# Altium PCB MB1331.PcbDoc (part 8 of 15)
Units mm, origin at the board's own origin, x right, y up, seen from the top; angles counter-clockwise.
Board outline 169.25 x 173.25 mm, 6 copper layers (Top Layer, Signal Layer 1, Signal Layer 2, Signal Layer 3, Signal Layer 4, Bottom Layer), stack 1.556 mm thick; 871 components, 699 nets, 3244 pads, 2370 vias.
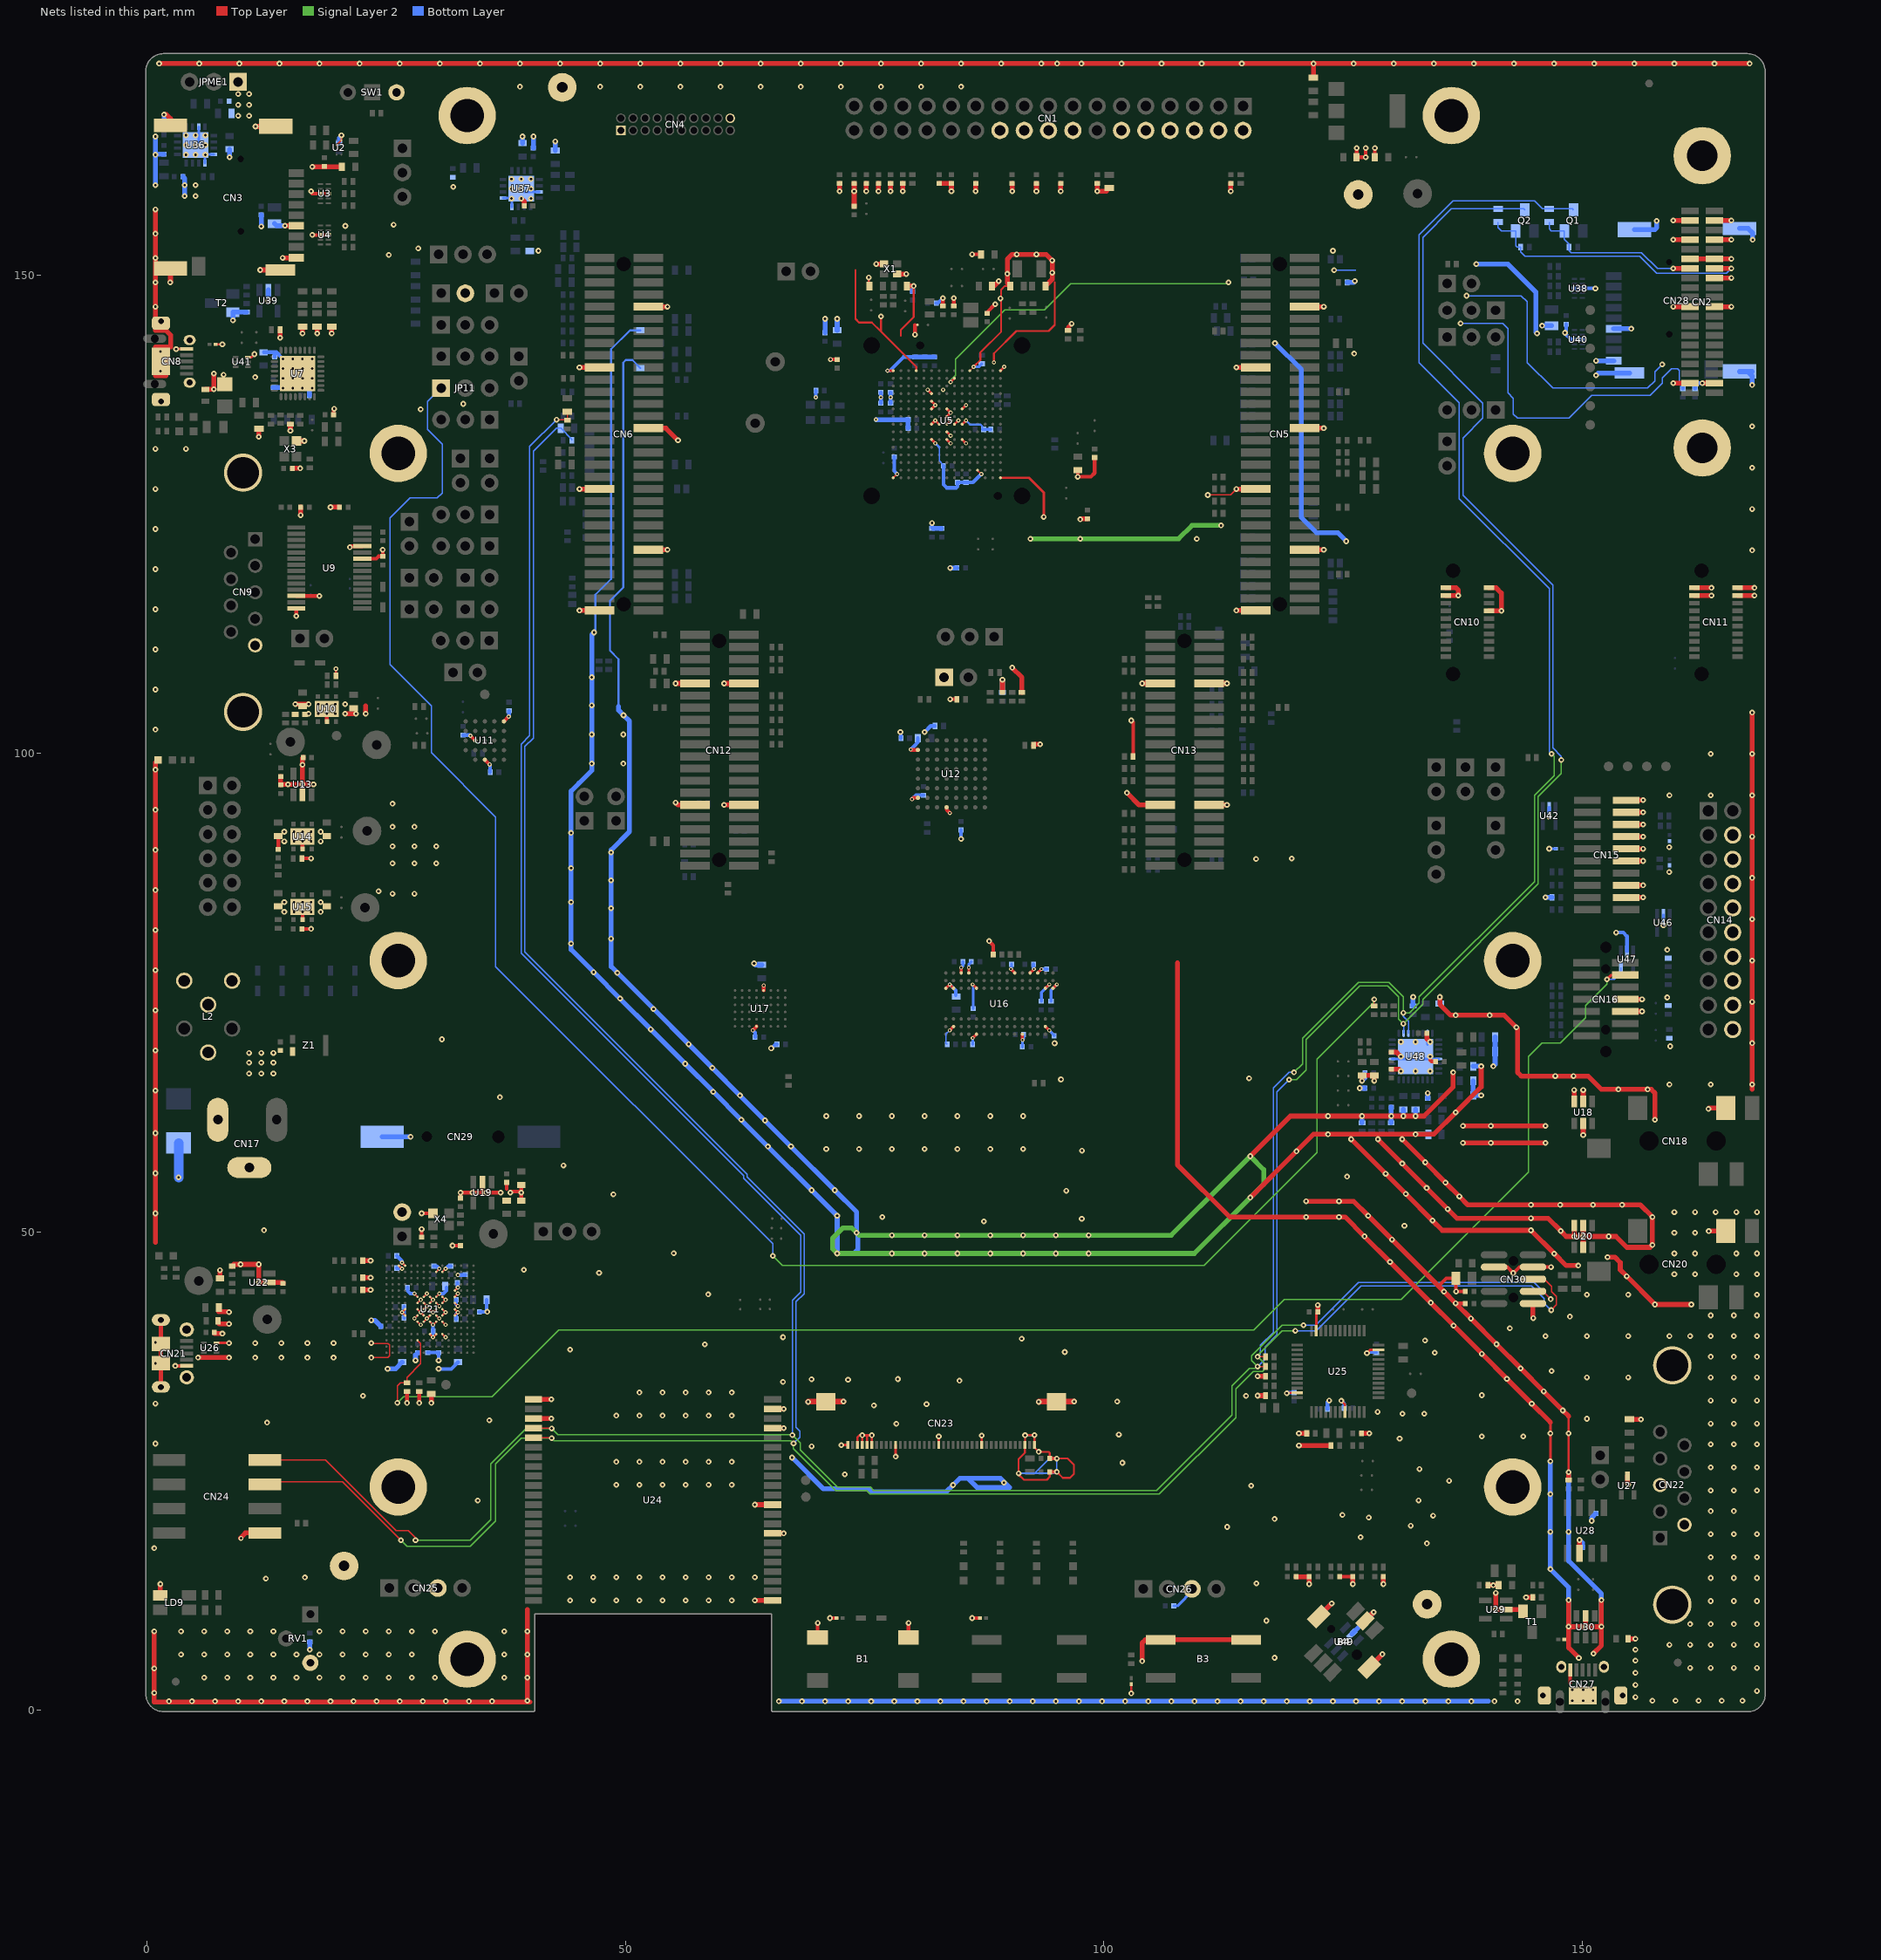
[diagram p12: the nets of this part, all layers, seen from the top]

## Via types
v1: diameter 0.6, hole 0.254, Top Layer to Bottom Layer, tented both sides, 1747 vias
v2: diameter 0.45, hole 0.2, Top Layer to Bottom Layer, tented both sides, 272 vias
v3: diameter 0.406, hole 0.203, Top Layer to Bottom Layer, tented both sides, 160 vias
v4: diameter 0.6, hole 0.25, Top Layer to Bottom Layer, tented both sides, 82 vias
v5: diameter 0.45, hole 0.25, Top Layer to Bottom Layer, tented both sides, 45 vias
v6: diameter 0.5, hole 0.25, Top Layer to Bottom Layer, tented both sides, 23 vias
v7: diameter 1.016, hole 0.508, Top Layer to Bottom Layer, tented both sides, 17 vias
v8: diameter 0.508, hole 0.254, Top Layer to Bottom Layer, tented both sides, 9 vias
v9: diameter 0.61, hole 0.305, Top Layer to Bottom Layer, tented both sides, 7 vias
v10: diameter 0.5, hole 0.254, Top Layer to Bottom Layer, tented both sides, 6 vias
v11: diameter 0.4, hole 0.2, Top Layer to Bottom Layer, tented both sides, 1 vias
v12: diameter 0.483, hole 0.254, Top Layer to Bottom Layer, tented both sides, 1 vias

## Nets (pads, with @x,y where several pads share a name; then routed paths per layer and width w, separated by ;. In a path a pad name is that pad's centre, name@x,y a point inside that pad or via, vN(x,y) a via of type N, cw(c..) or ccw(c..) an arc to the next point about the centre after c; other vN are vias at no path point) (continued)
GND: B1.1 B1.2 B3.3 B3.4 B4.5 B4.7 B4.8 C1.1 C2.1 C3.2 C4.1 C5.1 C6.1 C7.1 C8.1 C9.1 C10.1 C11.1 C12.1 C13.1 C14.1 C15.1 C16.1 C17.1 C18.1 C19.1 C20.1 C21.1 C22.1 C23.1 C24.1 C25.1 C26.1 C27.1 C28.1 C29.1 C30.2 C31.2 C32.1 C33.2 C34.1 C35.2 C37.1 C38.1 C39.2 C41.2 C42.2 C43.2 C44.1 C45.2 C46.1 C47.1 C48.1 C49.2 C50.1 C51.2 C52.1 C53.1 C54.2 C55.2 C56.1 C58.1 C59.1 C60.2 C61.2 C62.2 C63.2 C64.1 C65.1 C66.1 C67.1 C68.1 C69.1 C70.1 C71.1 C72.2 C73.2 C74.2 C75.1 C76.2 C77.1 C78.1 C79.1 C80.1 C81.1 C82.1 C83.1 C84.1 C85.1 C86.1 C87.1 C88.1 C89.1 C90.1 C91.1 C92.2 C93.2 C94.1 C95.1 C96.2 C97.2 C98.2 C99.2 C100.2 C101.2 C102.1 C103.2 C104.2 C105.1 C106.1 C107.1 C108.1 C109.1 C110.2 C111.2 C112.2 C113.2 C114.1 C115.1 C116.2 C117.2 C118.1 C119.2 C120.2 C121.2 C122.2 C123.2 C124.2 C125.2 C126.2 C127.2 C128.2 C129.2 C130.2 C131.1 C132.1 C133.1 C134.2 C135.1 C136.2 C137.2 C138.2 C139.2 C140.2 C141.2 C142.1 C143.2 C144.1 C145.2 C146.2 C147.1 C149.2 C150.2 C152.2 C153.2 C154.2 C155.2 C156.2 C157.2 C158.2 C160.1 C161.1 C162.2 C163.1 C165.2 C166.2 C167.2 C168.1 C171.1 C172.1 C173.1 C174.1 C175.1 C176.1 C177.1 C178.1 C179.1 C180.1 C181.1 C182.1 C183.1 C184.1 C185.1 C186.1 C187.1 C188.1 C189.1 C190.1 C191.1 C192.1 C193.1 C194.1 C195.1 C196.2 C197.2 C198.1 C199.2 C200.1 C201.1 CN1.2 CN1.4 CN1.6 CN1.8 CN1.10 CN1.12 CN1.16 CN1.18 CN1.20 CN1.22 CN2.3 CN2.4 CN2.7 CN2.8 CN2.11 CN2.12 CN2.16 CN2.21 CN2.22 CN2.37 CN2.38 CN2.41 CN2.42 CN3.6 CN3.9 CN3.11 CN3.12 CN3.13 CN3.14 CN4.1 CN4.20 CN5.10 CN5.19 CN5.30 CN5.39 CN5.50 CN5.59 CN6.10 CN6.19 CN6.30 CN6.39 CN6.50 CN6.59 CN7.2 CN8.5 CN8.6 CN8.7 CN8.8 CN8.9 CN8.10 CN9.5 CN9.MT1 CN9.MT2 CN10.13 CN10.18 CN10.19 CN10.20 CN11.17 CN11.18 CN11.19 CN11.20 CN12.9 CN12.10 CN12.29 CN12.30 CN13.9 CN13.10 CN13.29 CN13.30 CN14.4 CN14.6 CN14.8 CN14.10 CN14.12 CN14.14 CN14.16 CN14.18 CN14.20 CN15.3 CN15.5 CN15.9 CN15.11 CN15.13 CN15.15 CN15.17 CN15.19 CN16.5 CN16.7 CN18.3 CN19.2 CN20.3 CN21.5 CN21.6 CN21.7 CN21.8 CN21.9 CN21.10 CN21.11 CN22.3 CN22.6 CN22.MT1 CN22.MT2 CN23.1 CN23.3 CN23.12 CN23.21 CN23.30 CN23.35 CN23.36 CN23.37 CN23.38 CN23.40 CN23.MT1 CN23.MT2 CN24.2 CN25.3 CN26.3 CN27.5 CN27.6 CN27.7 CN27.8 CN27.9 CN27.10 CN28.6 CN28.9 CN28.11 CN28.12 CN28.13 CN28.14 CN29.2 CN30.1 CN30.7 CN30.8 H1.1 H2.1 H3.1 H4.1 H5.1 H6.1 H7.1 H8.1 H9.1 H10.1 JP25.1 JPME1.1 L2.4 L2.5 L2.6 LD7.2 LD9.1 R1.1 R7.1 R25.1 R26.1 R27.1 R28.2 R30.2 R37.2 R40.1 R86.1 R90.1 R92.1 R100.2 R107.1 R109.1 R129.2 R147.2 R148.2 R151.1 R154.1 R163.2 R164.1 R165.1 R167.2 R169.1 R171.1 R172.1 R175.2 R188.2 R191.1 R198.1 R199.1 R200.1 R232.1 R251.2 R336.1 R346.1 R393.1 R395.1 R400.1 R402.2 R408.1 R410.1 R412.1 R414.1 R416.1 R419.2 R420.1 RV1.3 SB10.1 SW1.3 T1.2 T2.2 TPG1.1 TPG2.1 TPG3.1 TPG4.1 U2.2 U2.8 U3.3 U3.8 U4.3 U4.8 U5.A1 U5.A15 U5.D14 U5.E1 U5.F6 U5.F8 U5.F10 U5.G2 U5.G8 U5.H6 U5.H7 U5.H8 U5.H9 U5.H10 U5.J8 U5.K4 U5.K5 U5.K6 U5.K8 U5.K10 U5.M1 U5.R1 U5.R15 U6.2 U7.33 U8.2 U9.12 U9.14 U9.23 U9.25 U10.2 U10.EP U11.B3 U11.C1 U11.E5 U12.E8 U12.H2 U12.H7 U13.2 U14.2 U14.EP U15.2 U15.EP U16.A3 U16.B3 U16.B8 U16.C1 U16.D1 U16.E9 U16.F1 U16.L3 U16.L9 U16.M1 U16.N1 U16.P3 U16.P8 U16.R3 U17.D1 U17.E6 U18.2 U18.5 U18.6 U19.2 U20.2 U20.5 U20.6 U21.D5 U21.D6 U21.D7 U21.D8 U21.D9 U21.F2 U21.F6 U21.F7 U21.F8 U21.F9 U21.F10 U21.F12 U21.G2 U21.G6 U21.G7 U21.G8 U21.G9 U21.G10 U21.G12 U21.H6 U21.H7 U21.H8 U21.H9 U21.H10 U21.H12 U21.J6 U21.J7 U21.J8 U21.J9 U21.J10 U21.K6 U21.K7 U21.K8 U21.K9 U21.K10 U21.M1 U21.M8 U21.M9 U21.N1 U22.2 U23.2 U24.1 U24.3 U24.23 U24.30 U24.33 U24.41 U24.43 U25.8 U25.23 U25.35 U25.47 U26.3 U27.3 U28.2 U29.2 U30.2 U31.2 U32.2 U33.2 U34.2 U35.2 U36.7 U36.12 U36.13 U36.17 U37.7 U37.12 U37.13 U37.17 U38.3 U38.8 U39.2 U40.3 U40.8 U41.3 U42.2 U43.2 U44.2 U45.2 U46.2 U47.2 U48.7 U48.13 U48.28 U48.33 U49.2 X1.2 X1.4 X3.2 X4.2 | length 1998.9
  Top Layer w0.1: U5.E1@86,140 v2(86.4,140.4)
  Top Layer w0.127: v1(23.431,36.862) 25.158,36.862 25.35,37.054 25.35,38.191 25.191,38.35 23.467,38.35 v1(23.431,38.386) ; U5.D14@86.8,129.6 v2(87.2,129.2) ; v1(110.871,127) 110.905,127.034 113.25,127.034 v1(113.85,127.635) ; CN16.5@154.492,73.048 CN16.5@154.5,73.04 ; CN16.7@154.492,74.318 CN16.7@154.5,74.31
  Top Layer w0.2: U21.N1@26.325,46.475 v2(26.65,46.15) ; v2(26.65,46.8) U21.M1@26.975,46.475 ; U21.M9@26.975,41.275 v2(26.65,41.6) U21.M8@26.975,41.925 ; v2(27.95,40.95) U21.K9@28.275,41.275 ; v2(27.95,43.55) U21.K6@28.275,43.225 ; U21.K10@28.275,40.625 v2(28.6,40.3) ; U21.K8@28.275,41.925 v2(28.6,41.6) U21.J9@28.925,41.275 ; U21.K7@28.275,42.575 v2(28.6,42.9) ; U21.J10@28.925,40.625 v2(29.25,40.95) U21.H9@29.575,41.275 ; U21.J8@28.925,41.925 v2(29.25,42.25) U21.J7@28.925,42.575 ; U21.J6@28.925,43.225 v2(29.25,43.55) ; U21.H12@29.575,39.325 v2(29.9,39) U21.G12@30.225,39.325 ; U21.H10@29.575,40.625 v2(29.9,40.3) U21.G10@30.225,40.625 ; U21.H8@29.575,41.925 v2(29.9,41.6) U21.G8@30.225,41.925 ; U21.H7@29.575,42.575 v2(29.9,42.9) U21.H6@29.575,43.225 ; U21.G9@30.225,41.275 v2(30.55,40.95) ; U21.G7@30.225,42.575 v2(30.55,42.25) ; U21.G6@30.225,43.225 v2(30.55,43.55) ; U21.G2@30.225,45.825 v2(30.55,46.15) ; U21.F12@30.875,39.325 v2(31.2,39) ; U21.F10@30.875,40.625 v2(31.2,40.3) ; U21.F9@30.875,41.275 v2(31.2,41.6) U21.F8@30.875,41.925 ; U21.F7@30.875,42.575 v2(31.2,42.9) U21.F6@30.875,43.225 ; U21.F2@30.875,45.825 v2(31.2,46.15) ; U21.D9@32.175,41.275 v2(32.5,41.6) U21.D8@32.175,41.925 ; U21.D7@32.175,42.575 v2(32.5,42.25) ; U21.D6@32.175,43.225 v2(32.5,43.55) ; U21.D5@32.175,43.875 v2(32.5,44.2) ; CN12.10@62.373,107.3 CN12.10@62.373,107.315 ; 74.041,150.495 74.041,145.415 74.422,145.034 75.766,145.034 76.708,144.092 ; v1(75.438,149.733) 75.438,148.906 C22.1@75.5,148.844 ; v1(76.708,145.669) 76.708,144.092 ; 78.796,143.647 78.796,144.25 80.137,145.591 v1(80.137,148.844) ; U5.M1@80.4,140 80.4,140.4 76.708,144.092 ; v2(86.4,140.4) 87.1,141.1 87.1,141.9 89.281,144.081 89.281,148.463 89.662,148.844 C25.1@90.232,148.844 ; CN23.12@87.25,27.738 v1(87.25,28.725) ; C29.1@87.8,146 C29.1@87.8,146.093 ; v2(88.519,140.843) 88.519,141.8 90.864,144.145 94.234,144.145 94.869,144.78 94.869,149.225 ; C200.1@94.358,24.927 94.358,24.408 94.05,24.1 91.65,24.1 91.1,24.65 v1(91.1,24.775) 91.1,26.272 91.75,26.922 CN23.3@91.75,27.738 91.775,27.763 v1(91.775,28.75) 91.8,28.775 v1(92.75,28.775) CN23.1@92.75,27.738 92.75,27.475 v1(93.2,27.025) 94.25,27.025 94.358,26.917 C201.1@94.358,26.327 ; v1(95.1,24.925) 95.725,24.3 96.475,24.3 96.875,24.7 96.875,25.675 96.225,26.325 v1(95.1,26.325) ; CN16.5@154.5,73.04 CN16.5@154.532,73.085 ; CN16.7@154.5,74.31 CN16.7@154.532,74.355
  Top Layer w0.203: U2.2@19.816,163.572 U2.8@20.316,164.072 20.316,164.588 v1(20.32,164.592) ; U5.R15@78,128.8 v2(78.4,129.2) ; R30.2@96.266,144.214 96.266,144.526
  Top Layer w0.25: U41.3@10.556,141.412 10.912,141.412 v1(11.225,141.725) ; v1(72.575,27.725) 72.588,27.738 CN23.40@73.25,27.738 ; CN23.38@74.25,27.738 74.25,28.525 74.475,28.75 v1(74.75,28.75) ; CN23.37@74.75,27.738 v1(74.75,28.75) ; CN23.36@75.25,27.738 75.25,28.725 75.225,28.75 ; CN23.35@75.75,27.738 v1(75.75,28.75) 75.225,28.75 ; v1(78.25,26.525) CN23.30@78.25,27.738 ; CN23.21@82.75,27.738 v1(82.75,28.625) ; v1(74.75,28.75) 75.225,28.75
  Top Layer w0.254: v1(3.048,142.24) 3.078,142.27 CN8.5@4.13,142.27 ; U6.2@7.17,142.748 v1(7.874,142.748) ; U26.3@7.25,38.4 8.558,38.4 v1(8.572,38.386) ; R90.1@19.75,108.1 v6(19.75,108.85) ; v2(77.4,140) U5.R1@78,140 ; v2(81.6,138) U5.K4@82,137.6 ; v2(82.4,134.8) U5.J8@82.8,134.4 ; U5.H10@83.6,132.8 v2(84,132.4) ; U5.H9@83.6,133.6 v2(84,133.2) ; U5.H8@83.6,134.4 v2(84,134.8) ; U5.H7@83.6,135.2 v2(84,135.6) U5.H6@83.6,136 ; v2(84,138.8) U5.G2@84.4,139.2 ; U5.G8@84.4,134.4 v2(84.8,134.8) ; U5.F10@85.2,132.8 v2(85.6,132.4) ; U5.F8@85.2,134.4 v2(85.6,134.8) ; U5.F6@85.2,136 v2(85.6,136.4) ; U5.A15@89.2,128.8 92.18,128.8 93.726,127.254 v1(93.726,124.714) ; U5.A1@89.2,140 v2(89.6,140.4) ; v1(102.87,1.778) U35.2@102.87,2.736 ; v1(119.126,33.147) 119.162,33.183 U25.47@120.21,33.183 ; U25.35@122.21,39.683 122.21,41.496 C73.2@122.37,41.656 ; v1(124.829,32.357) 125.21,31.976 U25.8@125.21,31.183 ; v1(127.508,37.338) 127.853,37.683 U25.23@128.71,37.683 ; v1(146.685,26.035) v1(146.685,28.956) 146.685,30.099 ; v1(148.59,24.892) v1(148.59,28.956) 148.59,30.734 ; v1(163.195,62.865) v1@163.275,62.945
  Top Layer w0.3: U5.K10@82,132.8 v2(82.4,132.4) ; U5.K8@82,134.4 v2(82.4,134.8) ; U5.K6@82,136 v2(82.4,136.4) U5.K5@82,136.8
  Top Layer w0.305: U16.R3@83.497,75.463 v3(83.897,75.863) U16.P3@84.297,75.463 ; v3(83.896,71.063) U16.P8@84.297,71.463 ; U16.N1@85.097,77.063 v3(85.097,77.622) ; U16.M1@85.897,77.063 v3(85.897,77.622) ; v3(86.296,70.263) U16.L9@86.697,70.663 ; v3(86.296,75.863) U16.L3@86.696,75.463 ; v3(90.297,77.463) U16.F1@90.697,77.063 ; v3@91.497,70.066 U16.E9@91.497,70.663 ; U16.D1@92.297,77.063 v3(92.696,77.463) ; U16.C1@93.097,77.063 v3(93.496,77.463) ; U16.B8@93.897,71.463 v3(94.297,71.063) ; U16.B3@93.897,75.463 v3(94.296,75.863) ; U16.A3@94.697,75.463 v3(95.097,75.863)
  Top Layer w0.381: v1(2.953,36.005) 2.957,36 CN21.5@4.15,36 ; v1(15.6,114.35) U9.14@15.6,115.155 ; U9.12@15.6,116.455 v1@18.02,116.455 ; C54.2@16.198,81.661 v1(17.145,81.661) ; R129.2@16.198,89.027 v1(17.145,89.027) ; U15.2@16.256,82.647 v1(16.256,83.439) U15.EP@16.256,83.947 ; v1(17.145,158.75) 17.399,158.496 ; v1(17.272,154.178) U4.8@18.132,154.178 U4.3@18.952,154.178 ; v1@17.272,158.496 17.399,158.496 ; U10.2@18.796,103.348 v1(18.796,104.14) ; U3.3@18.952,158.496 U3.8@18.132,158.496 17.399,158.496 ; C32.1@19.5,135.382 19.5,135.959 v1(19.558,136.017) ; v1(21.209,121.539) 21.325,121.655 U9.25@22.5,121.655 ; U9.23@22.5,120.355 23.962,120.355 24.199,120.592 C41.2@24.638,120.592 v1(24.638,121.285) ; v1(27.178,32.131) R164.1@27.178,33.332 ; v1(28.448,32.131) R165.1@28.448,33.332 ; C68.1@28.702,49.472 v1(28.702,50.292) ; v1(28.702,51.943) 28.712,51.933 X4.2@29.909,51.933 ; v1(31.935,48.572) C69.1@32.766,48.572 ; C65.1@32.766,53.536 v1(32.766,54.102) v1(34.036,54.102) 35.052,54.102 ; v2(33.812,101.84) U11.B3@34.306,101.346 ; U19.2@35.052,55.202 35.052,54.102 ; U11.C1@35.306,99.346 v2(35.8,98.852) ; v1(36.957,54.102) v1(35.433,54.102) 35.052,54.102 ; U11.E5@37.306,103.346 v2(37.8,103.84) ; 37.592,54.483 C64.1@37.592,55.176 ; v1@37.973,54.229 v1@39.116,54.229 ; C67.1@39.116,53.532 v1(39.116,54.102) v1@39.116,54.229 ; C63.2@39.116,54.926 v1@39.116,54.229 ; v3(63.316,71.069) 63.703,71.456 U17.E6@63.703,71.48 ; U17.D1@64.453,75.23 v3(64.452,75.762) ; B1.1@70.093,7.637 70.093,9.133 v1(70.104,9.144) ; v1(71.374,9.652) U31.2@72.078,9.652 ; v6(71.443,141.166) C30.2@72.136,141.166 ; B1.2@79.593,7.637 79.593,9.133 v1(79.604,9.144) ; v3(79.827,100.419) 79.88,100.366 U12.H2@80.567,100.366 ; v3(79.953,95.212) 80.107,95.366 U12.H7@80.567,95.366 ; v1(80.264,143.764) 80.264,144.78 ; C27.1@83.185,147.004 v1(83.185,147.574) ; U12.E8@83.567,94.366 83.567,94.125 v3(83.915,93.777) ; v1(83.947,105.664) R92.1@84.64,105.664 ; C28.1@84.328,146.754 v1(84.328,147.574) ; v1(86.233,9.652) U32.2@87.064,9.652 ; v1(86.233,152.146) C21.1@87.184,152.146 ; C29.1@87.8,146.093 v1(88.646,146.939) ; v1(88.011,80.391) 88.45,79.952 C55.2@88.45,78.994 ; C200.1@94.358,24.927 95.098,24.927 v1(95.1,24.925) ; C201.1@94.358,26.327 95.098,26.327 v1(95.1,26.325) ; 96.266,144.526 v1(96.647,144.907) ; C33.2@97.282,129.602 v1(97.282,128.905) 98.655,128.905 99.05,129.3 C35.2@99.05,130.925 ; v1(102.87,103.441) 103.066,103.246 R109.1@103.066,99.695 ; C82.1@124.656,13.97 C83.1@126.042,13.97 ; v4(126.43,163.257) C1.1@126.43,162.306 v4(127.381,162.306) v4(127.381,163.257) ; C2.1@128.332,162.306 v4(128.332,163.257) ; v4(134.112,68.326) 134.112,67.945 134.239,67.818 C59.1@134.678,67.818 ; 134.962,44.362 135.012,44.362 135.8,45.15 C75.1@136.8,45.15 136.8,43.8 v1(136.825,43.775) C76.2@137.8,43.775 ; v1(136.775,42.549) 136.799,42.525 C79.1@137.8,42.525 ; CN30.8@140.795,46.33 142.17,46.33 v1(142.8,45.7) 142.835,45.7 143.465,46.33 CN30.7@144.865,46.33 146.745,46.33 v1(146.75,46.325) ; 148.755,2.855 CN27.5@148.755,4.23
  Top Layer w0.4: C51.2@13.716,89.985 C49.2@13.716,91.375 ; U14.2@16.256,90.013 v1(16.256,90.805) U14.EP@16.256,91.313 ; v1(18.796,104.14) U10.EP@18.796,104.648
  Top Layer w0.5: CN21.8@1.45,33.8 CN21.9@1.45,40.8 ; v6@9.779,18.034 10.29,18.545 CN24.2@12.308,18.545 ; v1(113.85,114.935) CN5.59@115.872,114.935 ; v1(113.85,140.335) CN5.19@115.872,140.335 ; CN5.50@120.972,121.285 v1(122.994,121.285) ; CN5.30@120.972,133.985 v1(122.994,133.985) ; CN30.1@144.865,42.52 144.865,41.035 v1(144.9,41)
  Top Layer w0.508: v1(0.762,8.255) v1(0.762,4.381) v1(0.762,1.841) 0.762,0.889 v1@40.005,0.889 ; 0.889,48.895 v1(0.889,51.943) v1(0.889,56.134) v1(0.889,60.325) v1(0.889,64.77) v1(0.889,68.961) v1(0.889,73.152) v1(0.889,77.343) v1(0.889,81.534) v1(0.889,85.725) v1(0.889,89.916) v1(0.889,94.107) v1(0.889,98.298) 0.889,99.048 LD7.2@1.155,99.314 ; v1(0.889,156.845) v1(0.889,154.305) v1(0.889,151.765) v1(0.889,149.225) v1(0.889,146.685) 0.889,144.224 1.957,144.224 2.471,143.709 2.471,142.466 0.889,142.466 0.889,139.474 1.957,139.474 ; v1(1.27,172.085) v1(5.461,172.085) v1(9.652,172.085) v1(13.843,172.085) v1(18.034,172.085) v1(22.225,172.085) v1(26.416,172.085) v1(30.607,172.085) v1(34.798,172.085) v1(38.989,172.085) v1(43.18,172.085) v1(47.371,172.085) v1(51.562,172.085) v1(55.753,172.085) v1(59.944,172.085) v1(64.135,172.085) v1(68.326,172.085) v1(72.517,172.085) v1(76.708,172.085) v1(80.899,172.085) v1(85.09,172.085) v1(89.281,172.085) v1(93.472,172.085) v1(95.123,172.085) v1(97.663,172.085) v1(101.854,172.085) v1(106.045,172.085) v1(110.236,172.085) v1(114.427,172.085) v1(121.92,172.085) ; LD9.1@1.377,12.028 1.397,12.048 v1(1.397,13.208) ; v1(1.397,139.954) 1.455,140.012 CN8.10@1.455,140.97 1.397,141.028 v1(1.397,141.986) ; v1(1.778,166.751) 2.032,166.751 2.45,166.333 CN3.12@2.45,165.615 ; v1(2.413,149.225) 2.45,149.262 CN3.11@2.45,150.665 ; v1(5.334,36.862) v1(8.572,36.862) ; U8.2@6.096,138.039 6.975,138.039 v1(6.985,138.049) v1(6.985,139.7) ; C74.2@7.054,39.37 v1(7.874,39.37) ; C72.2@7.483,41.656 8.541,41.656 v1(8.572,41.624) ; U23.2@7.558,40.386 v1(8.572,40.386) ; C70.1@7.62,45.15 v1(7.62,46.006) ; R148.2@8.89,46.424 9.075,46.609 v1(9.779,46.609) v1(11.684,46.609) v1(11.684,44.704) U22.2@12.784,44.704 14.166,44.704 C71.1@14.224,44.646 ; v1(11.337,165.515) CN3.13@13.45,165.515 ; v1(11.684,133.096) R37.2@11.684,133.92 ; v1(11.831,150.515) CN3.14@13.95,150.515 ; v1(13.912,143.441) R28.2@13.912,144.272 ; C48.1@13.97,96.716 C47.1@13.97,97.594 ; C48.1@14.028,96.774 v1(14.732,96.774) v1(16.256,96.774) ; v1(14.17,151.79) CN3.9@15.6,151.79 ; v1(14.424,155.14) CN3.6@15.6,155.14 ; v1(14.986,133.731) R40.1@14.986,134.424 ; C34.1@15.182,129.794 v1(16.002,129.794) ; v1(15.494,105.156) v1(16.891,105.156) ; X3.2@15.611,132.651 v1(16.446,132.651) ; v1(16.06,124.899) C37.1@16.06,125.73 ; U13.2@16.256,95.674 v1(16.256,96.774) ; v1(16.256,143.891) R25.1@16.256,144.588 ; C46.1@16.314,99.568 16.256,99.51 v1(16.256,98.806) v1(16.256,96.774) ; v1(17.272,161.29) C3.2@18.542,161.29 ; v1(17.399,96.774) v1(16.256,96.774) ; v1(17.78,143.891) R26.1@17.78,144.588 ; C3.2@18.542,161.348 C3.2@18.542,161.29 ; v1(19.177,125.73) C38.1@20.124,125.73 ; v1(19.304,143.891) R27.1@19.304,144.588 ; C4.1@20.382,161.29 C3.2@18.542,161.29 ; v1(20.701,104.14) v1(21.844,104.14) ; R154.1@22.548,43.942 v1(23.368,43.942) ; R151.1@22.548,45.212 v1(23.368,45.212) ; R147.2@22.548,46.99 v1(23.368,46.99) ; v1(22.86,104.14) 22.86,104.96 ; v1(29.718,32.131) C77.1@29.718,33.082 ; v1(39.116,157.988) 39.428,157.676 C19.1@39.428,157.226 ; v1(39.751,1.016) v1(39.751,3.429) v1(39.751,5.842) v1(39.751,8.255) 39.751,10.541 ; U24.3@40.4,30.5 v1(42.271,30.5) ; U24.1@40.4,32.5 v1(42.271,32.5) ; v1(45.2,114.935) CN6.59@47.293,114.935 ; v1(45.2,127.635) CN6.39@47.293,127.635 ; v1(45.2,140.335) CN6.19@47.293,140.335 ; CN6.50@52.393,121.285 v1(54.4,121.285) ; CN6.30@52.393,133.985 54.229,133.985 v1(55.499,132.715) ; CN6.10@52.393,146.685 v1(54.4,146.685) ; v1(55.245,94.869) 55.499,94.615 CN12.29@57.273,94.615 ; v1(55.251,107.315) CN12.9@57.273,107.315 ; v1(60.325,94.615) CN12.30@62.373,94.615 ; v1(60.325,107.315) CN12.10@62.373,107.315 ; v1(63.529,11.5) U24.23@65.4,11.5 ; v1(63.529,21.5) U24.33@65.4,21.5 ; U24.41@65.396,29.504 U24.41@65.4,29.5 v1(66.544,29.5) ; U24.30@65.4,18.5 65.404,18.496 v1(66.548,18.496) ; U24.43@65.4,31.5 65.404,31.496 v1(66.548,31.496) ; v1(72.39,158.75) C5.1@72.39,159.57 ; C20.1@73.914,157.168 v1(73.914,158.75) C6.1@73.914,159.57 ; v1(75.184,158.75) C7.1@75.184,159.57 ; v1(76.217,151.147) X1.2@77.049,151.147 ; v1(76.454,158.75) C8.1@76.454,159.57 ; v1(77.724,158.75) C9.1@77.724,159.57 ; X1.4@78.399,150.097 v1(79.358,150.097) ; v1(78.994,158.75) C10.1@78.994,159.57 ; C23.1@79.44,148.844 v1(80.137,148.844) ; C11.1@82.804,159.57 C12.1@84.074,159.57 v1(84.074,158.75) ; v1(86.614,158.75) C13.1@86.614,159.57 ; C24.1@88.33,148.844 88.519,148.844 v1(89.027,149.352) ; C43.2@89.408,106.368 v1(89.408,107.696) ; C25.1@90.232,148.844 89.916,149.16 v1(89.916,150.114) 89.916,151.638 90.424,152.146 v1(92.964,152.146) 93.98,152.146 v1(94.615,151.511) v1(94.615,150.241) 94.615,149.541 C26.1@93.918,148.844 ; v1(90.424,108.966) 91.44,107.95 R86.1@91.44,106.368 ; v1(90.424,158.75) C14.1@90.424,159.57 ; R107.1@92.652,100.838 92.779,100.965 v1(93.345,100.965) ; v1(92.964,158.75) C15.1@92.964,159.57 ; v1(95.504,158.75) C16.1@95.504,159.57 ; v1(97.536,124.46) 97.594,124.518 C39.2@98.298,124.518 ; C17.1@99.314,159.57 v1(99.314,158.75) 100.268,158.75 R7.1@100.584,159.066 ; v1(102.425,95.885) 103.696,94.615 CN13.29@105.892,94.615 ; v1(104.013,5.143) 104.013,7.048 104.355,7.39 B3.4@105.968,7.39 B3.3@114.868,7.39 ; v1(104.013,107.315) CN13.9@105.892,107.315 ; 107.696,78.105 107.696,57.023 113.157,51.562 v1(121.158,51.562) v1(124.587,51.562) 125.222,51.562 v1(127.249,49.535) v1(129.923,46.861) v1(134.18,42.604) v1(136.57,40.214) v1(139.525,37.259) v1(142.133,34.651) v1(144.736,32.048) 146.685,30.099 ; CN13.30@110.992,94.615 v1(112.881,94.615) ; CN13.10@110.992,107.315 v1(112.881,107.315) ; v1(113.284,158.75) C18.1@113.284,159.57 ; v1(113.85,127.635) CN5.39@115.872,127.635 ; v1(115.316,53.594) v1(120.142,58.42) 121.92,60.198 v1(123.444,60.198) v1(132.588,60.198) 134.493,60.198 v1(136.779,62.484) 139.446,65.151 v1(139.446,67.31) ; v1(115.316,57.912) 119.507,62.103 v1(123.444,62.103) v1(127,62.103) v1(130.048,62.103) v1(131.318,62.103) v1(132.588,62.103) 133.477,62.103 136.525,65.151 v1(136.525,66.675) ; v1(116.078,32.893) R167.2@116.898,32.893 ; v1(116.078,34.925) R163.2@116.898,34.925 ; C80.1@120.084,13.97 C81.1@121.47,13.97 v1(121.47,13.208) ; v1(120.396,27.686) R172.1@123.756,27.686 ; v1(120.396,28.956) R171.1@121.216,28.956 ; CN5.10@120.972,146.685 v1(122.994,146.685) ; v1(121.158,53.213) v1(124.587,53.213) 126.111,53.213 v1(127.635,51.689) v1(130.125,49.199) 134.962,44.362 v1(135.564,43.76) v1(136.775,42.549) ; R1.1@121.92,170.626 v1(121.92,172.085) ; C73.2@122.37,41.656 v1(122.37,42.36) ; B4.7@122.459,9.818 123.818,11.176 v1(123.825,11.176) ; v1(125.857,59.69) v1(129.464,56.083) v1(131.572,53.975) v1(134.357,51.19) 135.382,50.165 v1(144.653,50.165) v1(147.088,47.73) 148.336,46.482 v1(149.606,46.482) ; v1(126.042,13.208) C83.1@126.042,13.97 ; C78.1@126.942,28.956 v1(127.762,28.956) ; v1(127,65.786) C60.2@127,66.356 C61.2@128.27,66.356 v1(128.27,65.786) ; B4.5@127.303,9.358 v1(128.213,10.268) ; B4.8@127.763,4.514 129.121,5.873 v1(129.128,5.873) ; v1(128.651,59.69) v1(131.198,57.143) v1(133.749,54.592) v1(135.949,52.392) 136.906,51.435 v1(144.653,51.435) 146.431,51.435 v1(147.762,50.104) 148.336,49.53 v1(149.164,49.53) ; v1(129.228,13.208) C84.1@129.228,13.97 ; C62.2@130.048,66.998 130.868,66.998 v4(131.064,66.802) ; C58.1@130.048,68.776 130.614,68.776 v4(131.064,68.326) ; v1(131.191,59.69) v1(133.604,57.277) v1(135.723,55.158) v1(137.172,53.709) 138.049,52.832 v1(144.653,52.832) v1(147.701,52.832) v1(151.13,52.832) v1(154.178,52.832) 156.083,52.832 v1(157.353,51.562) v1(157.353,48.641) 157.099,48.387 154.686,48.387 153.543,49.53 v1(152.781,49.53) v1(150.114,49.53) ; C56.1@133.788,70.751 133.788,70.174 v4(134.112,69.85) ; v1(135.128,74.549) 135.128,73.787 136.271,72.644 v1(136.779,72.644) v1(140.335,72.644) 141.859,72.644 v1(143.129,71.374) 143.256,71.247 143.256,66.675 143.637,66.294 v1(147.193,66.294) v1(149.098,66.294) 150.622,66.294 152.019,64.897 v1(153.797,64.897) v1(156.845,64.897) 157.226,64.897 157.607,64.516 v1(157.607,61.722) ; CN10.18@135.75,116.5 v1(137.062,116.5) 137.062,117.065 136.827,117.3 CN10.20@135.75,117.3 ; v1@136.799,42.525 v1(138.376,40.948) v1(141.051,38.273) v1(143.574,35.75) v1(145.982,33.342) v1(147.978,31.346) 148.59,30.734 ; v1(137.541,59.309) v1(140.462,59.309) v1(146.177,59.309) ; v1(137.541,61.087) v1(140.462,61.087) v1(146.177,61.087) ; R188.2@140.15,13.081 v1(140.716,13.081) C85.1@141.286,13.081 ; CN10.13@140.25,114.9 v1(141.562,114.9) 141.562,116.756 141.018,117.3 CN10.19@140.25,117.3 ; v1(140.97,12.287) v1@140.97,10.668 ; T1.2@143.83,10.371 143.66,10.541 U29.2@142.07,10.541 v1@141.097,10.541 ; v1(144.145,11.811) R191.1@144.838,11.811 ; v1(148.59,11.525) v1(148.59,8.763) v1@148.59,8.534 ; R175.2@148.59,24.072 v1(148.59,24.892) ; U20.6@149.164,50.68 v1(149.164,49.53) ; U18.6@149.164,63.634 v1(149.164,64.836) ; v1(149.657,5.486) 148.59,6.553 v1@148.59,8.534 ; U28.2@149.733,16.421 v1(149.733,17.812) ; U20.2@150.114,48.38 v1(150.114,49.53) ; U20.5@150.114,50.68 v1(150.114,49.53) ; v1(150.114,60.132) U18.2@150.114,61.334 ; U18.5@150.114,63.634 v1(150.114,64.836) ; U30.2@150.368,9.837 v1(150.368,8.738) ; v1(151.181,5.944) 152.019,6.782 v1(152.019,8.763) v1(152.019,11.525) ; v1@151.892,8.738 v1(150.368,8.738) ; v1(152.654,47.371) 153.416,47.371 153.987,46.799 153.987,46.038 v1(154.656,45.369) v1(157.607,42.418) v1(161.417,42.418) ; CN16.5@154.5,73.04 v1(156.267,73.04) ; CN16.7@154.5,74.31 v1(156.267,74.31) ; CN15.3@154.608,84.955 v1(156.375,84.955) ; CN15.5@154.608,86.225 v1(156.375,86.225) ; CN15.9@154.608,88.765 v1(156.375,88.765) ; CN15.11@154.608,90.035 v1(156.375,90.035) ; CN15.13@154.608,91.305 v1(156.375,91.305) ; CN15.15@154.608,92.575 v1(156.375,92.575) ; CN15.17@154.608,93.845 v1(156.375,93.845) ; CN15.19@154.608,95.115 v1(156.375,95.115) ; v1@154.727,23.708 U27.3@154.727,24.47 ; U33.2@154.803,7.493 v1(155.575,7.493) ; R169.1@154.94,30.418 v1(156.148,30.418) ; v1(159.513,138.685) CN2.37@161.28,138.685 ; v1(159.513,146.685) CN2.21@161.28,146.685 ; v1(159.513,153.685) CN2.7@161.28,153.685 ; v1(159.513,155.685) CN2.3@161.28,155.685 ; CN2.11@161.28,151.685 CN2.12@163.83,151.685 v1(165.597,151.685) ; CN11.18@161.75,116.5 v1(163.517,116.5) ; CN11.20@161.75,117.3 v1(163.517,117.3) ; v1(162.56,138.684) 162.561,138.685 CN2.38@163.83,138.685 ; v1(163.237,50.08) CN20.3@165,50.08 ; v1@163.275,62.945 CN18.3@165.005,62.945 ; CN2.22@163.83,146.685 v1(165.597,146.685) ; CN2.16@163.83,149.685 v1(165.597,149.685) ; CN2.8@163.83,153.685 v1(165.597,153.685) ; CN2.4@163.83,155.685 v1(165.597,155.685) ; CN11.17@166.25,116.5 v1(168.017,116.5) ; CN11.19@166.25,117.3 v1(168.017,117.3) ; v1(167.513,172.085) v1(163.83,172.085) v1(159.639,172.085) v1(155.448,172.085) v1(151.257,172.085) v1(147.066,172.085) v1(142.875,172.085) v1(138.684,172.085) v1(134.493,172.085) v1(130.302,172.085) v1(126.111,172.085) v1(121.92,172.085) ; 167.767,64.897 v1(167.767,65.405) v1(167.767,69.723) v1(167.767,74.041) v1(167.767,78.359) v1(167.767,82.677) v1(167.767,86.995) v1(167.767,91.313) v1(167.767,95.631) v1(167.767,99.949) v1(167.767,104.267) ; v1@140.97,10.668 v1@141.097,10.541 ; v1@140.97,10.668 v1(140.97,10.541) v1@141.097,10.541 ; v1@148.59,8.534 148.793,8.738 v1(150.368,8.738) ; v1(149.164,49.53) v1(150.114,49.53)
  Top Layer w0.6: v1(69.1,32.25) 69.112,32.263 CN23.MT2@70.95,32.263 72.788,32.263 v1(72.8,32.275) ; v1(93.2,32.25) 93.212,32.263 CN23.MT1@95.05,32.263 96.888,32.263 v1(96.9,32.275)
  Signal Layer 2 w0.127: v2(84,138.8) 84,139 84.5,139.5 84.5,141.2 89.668,146.368 93.789,146.368 96.52,149.098 112.903,149.098 v1(113.03,149.225)
  Signal Layer 2 w0.508: v1(92.329,122.428) v1(97.536,122.428) 107.823,122.428 109.22,123.825 v1(112.268,123.825) ; 71.65,48.238 v1(72.136,47.752) v1(77.851,47.752) v1(81.28,47.752) v1(84.709,47.752) v1(88.138,47.752) v1(91.567,47.752) v1(94.996,47.752) v1(98.425,47.752) 109.474,47.752 v1(115.316,53.594) 116.713,54.991 116.713,56.515 v1(115.316,57.912) 112.903,55.499 107.061,49.657 v1(98.425,49.657) v1(94.996,49.657) v1(91.567,49.657) v1(88.138,49.657) v1(84.709,49.657) v1(81.28,49.657) v1(77.851,49.657) 74.422,49.657 v1(74.168,49.911) 73.654,50.425 72.75,50.425 71.65,49.325 71.65,48.238
  Bottom Layer w0.127: 82.8,132 82.8,130.56 83.243,130.117 C125.2@83.243,130.048 ; C155.2@83.439,69.781 C155.2@83.509,69.711 ; C155.2@83.624,69.596 C155.2@83.509,69.711 ; v3(83.896,71.063) 83.509,70.675 C155.2@83.509,69.711 ; 92.748,24.775 94.298,26.325 v1(95.1,26.325) v1(95.1,24.925) ; v1(124.079,150.495) 126.365,150.495 ; v1(137.3,144.934) 141.705,144.934 142.24,144.399 142.24,137.668 142.8,137.108 142.8,135.475 143.25,135.025 148.614,135.025 151.003,137.414 157.099,137.414 158.37,138.685 158.37,139.257 159.321,140.208 159.957,140.208 160.147,140.017 160.147,138.812 ; v1(137.922,147.828) 143.637,147.828 144.272,147.193 144.272,140.843 146.939,138.176 156.845,138.176 157.607,138.938 157.607,139.891 v1(158.369,140.653)
  Bottom Layer w0.2: v2(26.65,41.6) 26.795,41.6 26.866,41.529 ; v2(29.9,39) C186.1@29.9,39.65 v2(29.9,40.3) ; v2(30.55,43.55) v2@30.65,43.55 ; v2@32.5,41.586 v2(32.5,41.6) ; v1(91.1,24.775) 92.748,24.775 94.95,24.775 v1(95.1,24.925) ; v1(91.775,28.75) 91.8,28.775 v1(92.75,28.775)
  Bottom Layer w0.203: v1(46.736,112.649) 46.863,112.776 46.863,116.586 48.514,118.237 48.514,142.24 50.484,144.21 C103.2@51.562,144.21 ; 49.276,104.902 49.276,109.855 48.387,110.744 48.387,115.951 49.784,117.348 49.784,140.843 50.038,141.097 50.735,141.097 C106.1@51.562,140.27 ; v2(85.6,134.8) 86.034,134.366 87.122,134.366 87.318,134.17 C123.2@87.318,133.858
  Bottom Layer w0.254: U36.17@5.405,163.901 U36.7@5.405,165.476 ; U36.13@6.055,161.676 6.055,162.601 U36.12@6.98,162.601 ; U37.13@37.216,158.029 38.141,158.029 U37.12@38.141,157.104 ; U37.17@39.441,158.679 U37.7@41.016,158.679 ; v2(82.4,132.4) 82.8,132 ; v1(127.508,37.338) 127.566,37.396 C189.1@128.524,37.396 ; U48.28@130.163,68.076 U48.33@132.338,68.076 ; U48.33@132.838,68.076 U48.13@135.013,68.076 ; U48.33@133.838,69.576 U48.7@133.838,70.751 ; v1(146.558,90.043) U44.2@147.262,90.043 ; v1(158.496,82.042) U46.2@158.496,83.146
  Bottom Layer w0.3: C123.2@87.318,133.858 C123.2@87.445,133.858 C122.2@88.196,133.858 ; C198.1@107.315,10.923 107.69,10.923 109.34,12.573 CN26.3@109.22,12.7
  Bottom Layer w0.305: v3(85.097,77.622) 85.286,77.812 C139.2@85.286,78.232 ; v3(85.897,77.622) 85.897,77.965 C138.2@86.164,78.232 ; v3(86.296,70.263) 86.302,70.258 C154.2@86.302,69.596 ; C149.2@86.36,73.348 v3@86.36,75.8 ; v2(86.4,140.4) 86.933,140.4 R251.2@87.249,140.716 ; v3(90.297,77.463) 90.366,77.533 C141.2@90.366,77.978 ; C158.2@91.498,69.342 91.498,70.042 v3(91.51,70.053) 91.636,70.18 C150.2@91.636,70.612 ; C146.2@93.472,74.11 93.472,75.039 v3(94.296,75.863) ; v3(94.297,71.063) 94.811,70.549 C152.2@94.811,70.485 ; C145.2@94.488,74.11 94.488,75.255 v3(95.097,75.863)
  Bottom Layer w0.381: C105.1@12.192,141.924 13.516,141.924 v1(14.22,141.22) ; C110.2@13.335,141.42 13.335,141.743 ; R199.1@20.066,163.772 20.066,164.338 v1(20.32,164.592) ; C175.1@26.104,46.228 26.572,46.228 v2(26.65,46.15) ; C171.1@26.104,47.498 26.65,46.952 v2(26.65,46.8) ; C183.1@26.866,41.021 26.866,41.529 C181.1@26.866,42.164 ; C178.1@27.236,44.196 27.236,43.82 27.506,43.55 v2(27.95,43.55) ; C191.1@29.337,37.396 C190.1@30.48,37.396 v1(30.48,36.576) ; v2(29.9,39) v2(29.9,40.3) ; C174.1@29.972,46.424 30.276,46.424 v2(30.55,46.15) ; v1(30.48,35.687) 30.483,35.684 31.812,35.684 C187.1@32.512,36.384 ; v2@30.65,43.55 30.977,43.55 31.307,43.88 C177.1@31.307,44.196 ; v2(31.2,46.15) 31.474,46.424 C173.1@31.75,46.424 ; C184.1@32.316,40.894 32.316,41.402 v2@32.5,41.586 ; C180.1@32.316,42.926 32.316,42.434 v2(32.5,42.25) ; C176.1@32.443,44.704 32.443,44.257 v2(32.5,44.2) ; C132.1@33.02,101.912 33.74,101.912 v2(33.812,101.84) ; C172.1@33.25,45.5 C172.1@33.274,45.524 ; C182.1@34.74,41.656 v1(35.56,41.656) 35.498,41.718 C179.1@35.498,42.926 ; v2(35.8,98.852) 35.872,98.78 C135.1@35.872,98.044 ; v2(37.8,103.84) 37.846,103.886 C131.1@37.846,104.452 ; v3(63.316,71.069) 63.558,70.827 C153.2@63.558,70.358 ; v9@65.202,69.146 v9(65.246,69.19) 65.652,69.596 C156.2@65.844,69.596 ; v2(69.908,137.2) C116.2@69.908,137.922 ; C119.2@76.708,136.594 v2(76.708,137.2) C113.2@76.708,137.726 ; v2(77.4,140) 77.643,140 79.063,141.42 C109.1@80.264,141.42 ; C118.1@77.724,136.594 v2(77.724,137.2) C112.2@77.724,137.726 ; C124.2@78.105,130.995 78.105,129.495 v2(78.4,129.2) ; v1(78.74,102.235) 78.798,102.177 C134.2@78.798,101.6 ; v3(79.953,95.212) 80.374,95.633 C136.2@81.167,95.633 ; 80.334,100.876 79.876,100.419 v3(79.827,100.419) 80.58,101.172 C133.1@80.58,101.6 ; v1(81.28,102.235) 81.915,102.87 R346.1@82.354,102.87 ; C129.2@82.042,123.64 v1(82.042,124.079) ; C99.2@82.492,147.066 82.677,147.066 v1(83.185,147.574) ; C125.2@83.243,130.048 83.243,128.085 83.566,127.762 84.582,127.762 84.709,127.889 C127.2@84.709,128.328 C126.2@85.598,128.328 86.328,128.328 v2(87.2,129.2) ; v3(83.897,75.863) 84.525,75.235 C144.1@84.525,74.752 ; v1(85.09,91.059) C137.2@85.09,92.006 ; C140.2@92.652,77.978 92.652,77.508 v3(92.696,77.463) ; v3(93.496,77.463) 93.503,77.47 C143.2@94.038,77.47 ; v1(119.126,33.147) 119.195,33.216 C193.1@119.888,33.216 ; C195.1@123.386,31.496 123.386,32.2 v1(123.571,32.385) ; v1(124.829,32.357) 125.141,32.045 C194.1@125.141,31.595 ; v1(146.558,93.409) U42.2@146.558,94.322 ; v1(148.209,143.954) v1@148.209,143.891 ; C101.2@148.336,144.838 148.336,144.018 v1@148.209,143.891 ; U38.3@149.196,148.59 U38.8@150.016,148.59 v1(151.384,148.59) ; U40.8@150.016,143.256 U40.3@149.196,143.256 148.844,143.256 v1@148.209,143.891 ; v1(153.543,81.28) 154.305,81.28 154.686,80.899 U47.2@154.686,79.336 ; v1(159.513,138.685) 160.273,138.685 160.528,138.43 C115.1@160.528,138.118 ; C114.1@161.798,138.118 161.798,138.43 162.052,138.684 v1(162.56,138.684)
  Bottom Layer w0.4: v2(32.5,45.5) C172.1@33.25,45.5
  Bottom Layer w0.5: v1(117.894,142.875) 120.65,140.119 120.65,124.65 122.237,123.063 124.46,123.063 v1(125.349,122.174)
  Bottom Layer w0.508: v1(0.889,159.385) v1(0.889,162.56) ; v1(0.889,164.465) v1(0.889,162.56) ; C90.1@1.778,162.618 0.947,162.618 v1(0.889,162.56) ; C87.1@1.778,165.55 v1(1.778,166.751) ; C93.2@3.752,160.274 3.937,160.089 v1(3.937,159.385) v1(3.937,158.242) ; v1(8.636,162.306) C88.1@8.636,163.13 ; v1(8.974,145.245) T2.2@8.974,146.116 10.406,146.116 R232.1@10.414,146.108 ; v1(11.938,155.067) C95.1@11.938,156.268 ; v1(12.7,147.32) U39.2@12.7,148.42 ; C111.2@13.208,138.234 14.158,138.234 v1(14.22,138.172) ; C94.1@13.335,155.36 13.555,155.14 v1(14.424,155.14) ; C117.2@16.96,137.414 16.96,137.864 v1(17.268,138.172) ; v1(17.018,6.35) C199.2@17.018,7.17 ; v1(23.431,40.767) 23.807,40.767 C185.1@24.442,40.132 ; CN29.2@24.566,59.944 v1(27.559,59.944) ; v1(25.146,35.687) 25.149,35.684 26,35.684 26,35.714 C188.1@26.67,36.384 ; v1(28.067,36.576) 28.067,37.142 C192.1@28.321,37.396 ; C89.1@39.243,163.768 v1(39.243,164.465) ; C91.1@40.386,163.264 v1(40.386,164.465) ; R200.1@42.672,163.006 v1(42.672,163.957) ; 45.149,96.883 44.323,96.057 v1(44.323,91.694) v1(44.323,88.011) v1(44.323,84.455) v1(44.323,80.137) 44.323,79.502 v1(46.688,77.137) v1(49.443,74.382) v1(52.655,71.17) v1(56.251,67.574) v1(59.182,64.643) v1(62.113,61.712) v1(64.897,58.928) v1(69.469,54.356) v1(72.136,51.689) v1(72.136,47.752) 73.877,47.752 74.3,48.175 74.3,49.779 v1(74.168,49.911) 74.168,52.07 v1(71.882,54.356) v1(67.306,58.932) v1(64.588,61.65) v1(61.985,64.253) v1(59.096,67.142) v1(56.617,69.621) v1(52.94,73.298) v1(49.153,77.085) 48.514,77.724 v1(48.514,80.645) v1(48.514,83.82) v1(48.514,86.741) v1(48.514,89.662) 48.514,89.916 50.419,91.821 50.419,103.378 v1(49.807,103.99) 49.276,104.521 49.276,104.902 ; 45.149,96.883 46.482,98.216 v1(46.482,98.933) v1(46.482,101.981) v1(46.482,105.029) v1(46.482,107.95) 46.482,112.395 v1(46.736,112.649) ; v9(63.443,78.054) 63.581,77.916 C142.1@64.262,77.916 ; v1(66.04,0.953) v1(68.453,0.953) v1(70.866,0.953) v1(73.279,0.953) v1(75.692,0.953) v1(78.105,0.953) v1(80.518,0.953) v1(82.931,0.953) v1(85.344,0.953) v1(87.757,0.953) v1(90.17,0.953) v1(92.583,0.953) v1(94.996,0.953) v1(97.409,0.953) v1(99.822,0.953) v1(102.235,0.953) v1(104.648,0.953) v1(107.061,0.953) v1(109.474,0.953) v1(111.887,0.953) v1(114.3,0.953) v1(116.713,0.953) v1(119.126,0.953) v1(121.539,0.953) v1(123.952,0.953) v1(126.365,0.953) v1(128.778,0.953) v1(131.191,0.953) v1(133.604,0.953) v1(136.017,0.953) v1(138.43,0.953) 140.208,0.953 ; v1(67.425,26.425) 70.7,23.15 75.425,23.15 75.725,22.85 83.55,22.85 v1(84.25,23.55) 84.95,24.25 85.8,24.25 ; C104.2@70.866,143.96 v1(70.866,145.415) ; C102.1@72.136,144.21 v1(72.136,145.415) ; v2(76.2,134.874) C120.2@79.56,134.874 C121.2@79.56,133.985 ; C98.2@80.01,148.278 80.01,148.717 v1(80.137,148.844) ; C109.1@80.264,141.42 C108.1@81.28,141.42 C107.1@82.296,141.42 ; C129.2@82.169,123.513 C128.2@83.058,123.513 ; v1(83.947,119.38) C130.2@84.64,119.38 ; R336.1@89.408,106.368 v1(89.408,107.696) ; C97.2@125.418,149.225 126.111,149.225 v1(126.238,149.352) ; U49.2@125.924,7.979 v1(128.213,10.268) ; v1(126.746,65.024) C162.2@127.312,65.024 ; R419.2@127,61.41 v1(127,62.103) ; v1(127,65.786) 127.312,66.098 R414.1@127.312,66.548 ; R416.1@130.048,61.41 v1(130.048,62.103) C168.1@130.048,63.05 ; v1(131.318,62.103) C166.2@131.318,62.8 ; R402.2@132.334,73.602 v1(132.334,74.549) ; v1(132.588,60.198) R420.1@133.92,60.198 ; v1(132.588,62.103) C165.2@132.588,62.8 ; C167.2@133.858,63.95 v1(133.858,64.516) ; C147.1@135.128,73.852 v1(135.128,74.549) ; C161.1@138.622,65.786 C163.1@138.622,64.262 v1(139.446,64.262) ; C160.1@138.622,67.31 v1(139.446,67.31) ; v1(138.938,151.13) 142.24,151.13 145.167,148.203 145.167,144.012 v1(145.288,143.891) ; v1(140.716,67.31) 140.908,67.502 R412.1@140.908,68.834 R410.1@140.908,70.358 ; v1(145.821,144.692) C100.2@146.812,144.692 ; v1(146.177,84.963) R393.1@146.87,84.963 ; v1(146.685,26.035) v1(146.685,22.606) v1(146.685,18.669) v1(146.685,14.764) 148.59,12.859 v1(148.59,11.525) v1(148.59,8.763) ; v1(148.59,24.892) v1(148.59,18.669) 148.59,15.621 152.019,12.192 v1(152.019,11.525) v1(152.019,8.763) ; v1(149.733,17.812) 150.045,17.5 C197.2@150.045,17.018 ; v1(151.003,19.812) 151.003,20.135 C196.2@151.442,20.574 ; v1(151.447,139.51) 151.69,139.752 CN28.14@154.951,139.752 ; v1(151.447,141.034) 151.454,141.027 CN28.9@153.301,141.027 ; CN28.6@153.301,144.377 v1(155.13,144.377) ; CN28.13@155.451,154.752 157.609,154.752 157.797,154.94 v1(157.797,155.638) ; CN28.11@166.451,139.902 CN28.11@167.311,139.902 ; CN28.12@166.451,154.852 167.347,154.852 167.831,154.368 v1(167.831,153.67) ; CN28.11@167.756,139.902 CN28.11@167.311,139.902 ; v1(167.767,138.493) 167.767,139.446 CN28.11@167.311,139.902 ; 85.8,24.25 89.2,24.25 90.15,23.3 86.75,23.3 85.8,24.25
  Bottom Layer w1: v1(3.3,55.7) C157.2@3.3,59.3
  other v1: 2.286,0.953 4.699,0.953 7.112,0.953 9.525,0.953 11.938,0.953 14.351,0.953 16.764,0.953 19.177,0.953 21.59,0.953 24.003,0.953 26.416,0.953 28.829,0.953 31.242,0.953 33.655,0.953 36.068,0.953 140.843,0.953 143.256,0.953 148.971,1.016 150.114,1.016 151.13,1.016 157.353,1.016 159.766,1.016 162.179,1.016 164.592,1.016 166.751,1.016 155.575,1.397 168.275,2.032 148.971,2.159 150.114,2.159 151.13,2.159 155.575,2.667 5.969,3.429 8.382,3.429 10.795,3.429 13.208,3.429 15.621,3.429 18.034,3.429 20.447,3.429 22.86,3.429 25.273,3.429 27.686,3.429 30.099,3.429 37.338,3.429 155.575,3.937 161.29,4.445 163.449,4.445 165.862,4.445 168.275,4.445 155.575,5.207 117.85,5.5 3.556,5.842 5.969,5.842 8.382,5.842 10.795,5.842 13.208,5.842 15.621,5.842 18.034,5.842 20.447,5.842 22.86,5.842 25.273,5.842 27.686,5.842 37.338,5.842 155.575,6.35 159.131,6.858 161.29,6.858 163.449,6.858 165.862,6.858 168.275,6.858 3.556,8.255 5.969,8.255 8.382,8.255 10.795,8.255 13.208,8.255 18.034,8.255 20.447,8.255 22.86,8.255 25.273,8.255 27.686,8.255 30.099,8.255 37.338,8.255 161.29,9.017 163.449,9.017 165.862,9.017 168.275,9.017 117,9.375 163.449,11.43 165.862,11.43 168.275,11.43 44.225,11.5 46.638,11.5 49.051,11.5 51.464,11.5 53.877,11.5 56.29,11.5 58.703,11.5 61.116,11.5 115.95,13.275 12.425,13.775 163.449,13.843 165.862,13.843 168.275,13.843 16.5,13.9 44.225,13.913 46.638,13.913 49.051,13.913 51.464,13.913 53.877,13.913 56.29,13.913 58.703,13.913 61.116,13.913 63.529,13.913 163.449,16.002 165.862,16.002 168.275,16.002 0.762,16.954 133.775,17.45 126.85,18.1 163.449,18.415 165.862,18.415 168.275,18.415 112.9,19.175 132.08,19.304 117.85,20 127.7,20.15 134.425,20.35 124.95,20.425 163.449,20.828 165.862,20.828 34.575,21.925 132.9,21.95 163.449,22.987 165.862,22.987 168.275,22.987 115.4,23.475 49.051,23.565 51.464,23.565 53.877,23.565 56.29,23.565 58.703,23.565 61.116,23.565 154.813,23.622 89.575,23.8 136.1,24 72.925,24.675 133,25.225 163.449,25.4 165.862,25.4 168.275,25.4 101.95,25.875 49.051,25.978 51.464,25.978 53.877,25.978 56.29,25.978 58.703,25.978 61.116,25.978 69.475,27.6 163.449,27.813 165.862,27.813 168.275,27.813 0.889,27.877 130.925,28.4 139.525,28.623 143.843,28.623 101.575,28.825 78.325,29.95 163.449,29.972 165.862,29.972 168.275,29.972 12.55,30.075 35.775,30.325 150.495,30.48 49.051,30.804 51.464,30.804 53.877,30.804 56.29,30.804 58.703,30.804 61.116,30.804 131.225,31 133.5,31 128.625,31.2 75.975,31.875 81.475,32 0.889,32.067 101.4,32.275 163.449,32.385 165.862,32.385 168.275,32.385 22.575,32.875 114.875,32.875 139.525,32.941 51.464,33.217 53.877,33.217 56.29,33.217 58.703,33.217 61.116,33.217 66.475,34.325 84.925,34.45 73.275,34.55 69.45,34.6 78.475,34.625 150.495,34.798 154.813,34.798 163.449,34.798 165.862,34.798 168.275,34.798 146.8,35.475 0.889,36.258 11.303,36.862 14.034,36.862 16.764,36.862 19.494,36.862 163.449,36.957 165.862,36.957 168.275,36.957 134.6,37.375 95.925,37.45 44.225,37.7 58.3,38.25 11.303,38.386 14.034,38.386 16.764,38.386 19.494,38.386 0.889,38.449 133.575,38.65 91.425,38.85 66.475,39 146.177,39.116 150.495,39.116 154.813,39.116 159.131,39.116 161.29,39.116 163.449,39.116 165.862,39.116 168.275,39.116 142.45,39.925 148.725,41.15 163.449,41.275 165.862,41.275 168.275,41.275 150.495,43.434 154.813,43.434 168.275,43.434 58.65,43.475 159.639,45.593 161.798,45.593 166.116,45.593 168.275,45.593 47.25,45.725 39.4,46.05 159.639,47.752 161.798,47.752 166.116,47.752 168.275,47.752 55.05,47.775 159.639,49.911 161.798,49.911 12.225,50.175 131.425,50.65 87.475,51.1 97.7,51.375 76.85,51.55 159.639,52.07 161.798,52.07 163.957,52.07 166.116,52.07 168.275,52.07 48.75,53.925 37.973,54.102 96.075,54.3 125.425,55.775 43.525,56.95 97.725,58.5 70.993,58.674 74.422,58.674 77.851,58.674 81.28,58.674 84.709,58.674 88.138,58.674 91.567,58.674 70.993,62.103 74.422,62.103 77.851,62.103 81.28,62.103 84.709,62.103 88.138,62.103 91.567,62.103 36.875,64.075 159.131,65.405 163.449,65.405 115.189,66.04 159.2,69.4 30.825,70.125 158.9,74.5 158.9,79.479 14.351,83.439 15.367,83.439 17.145,83.439 18.161,83.439 14.351,84.455 15.367,84.455 16.256,84.455 17.145,84.455 18.161,84.455 159.1,87.6 115.925,88.975 119.65,89.025 159.1,90.2 14.351,90.805 15.367,90.805 17.145,90.805 18.161,90.805 14.351,91.821 15.367,91.821 16.256,91.821 17.145,91.821 18.161,91.821 159.131,95.631 163.449,95.631 49.784,98.933 163.449,99.949 49.784,101.981 0.889,102.489 16.891,104.14 17.907,104.14 19.685,104.14 17.907,105.156 18.796,105.156 19.685,105.156 20.701,105.156 0.889,106.68 0.889,110.871 0.889,115.062 18.025,116.45 0.889,119.253 167.767,121.221 109.728,122.428 0.889,123.444 167.767,125.539 0.889,127.635 167.767,129.857 0.889,131.826 4.064,131.826 167.767,134.175 28.6,135.95 33.05,136.525 15.232,138.176 16.248,138.176 14.224,139.192 15.236,139.196 16.252,139.196 17.272,139.192 11.303,139.319 8.001,139.573 14.224,140.208 15.236,140.212 16.252,140.212 17.272,140.208 15.232,141.224 16.248,141.224 17.268,141.22 126.175,141.775 89.2,147.55 25.275,152.1 90.9,152.15 40.911,152.525 123.952,152.527 28.35,152.775 20.725,155.125 25.775,155.25 38.1,157.988 40.132,157.988 5.08,158.242 38.1,159.004 39.116,159.004 40.132,159.004 32,159.2 5.08,159.385 38.1,160.02 39.116,160.02 40.132,160.02 4.064,162.56 5.08,162.56 6.096,162.56 4.064,163.576 5.08,163.576 6.096,163.576 4.064,164.592 5.08,164.592 6.096,164.592 9.525,166.624 10.668,166.624 9.525,167.767 10.668,167.767 9.525,168.91 10.668,168.91 38.989,169.672 47.371,169.672 51.562,169.672 55.753,169.672 59.944,169.672 64.135,169.672 68.326,169.672 72.517,169.672 76.708,169.672 80.899,169.672 85.09,169.672
  other v2: 83.2,138
  other v4: 132.588,66.802 134.112,66.802 132.588,68.326 131.064,69.85 132.588,69.85 25.654,85.344 27.94,85.344 24.2,85.6 25.654,88.519 27.94,88.519 30.226,88.519 25.654,90.297 27.94,90.297 30.226,90.297 25.654,92.329 27.94,92.329 25.654,94.742
  other v6: 9.831,17.982
  other v9: 95.523,65.938 94.869,69.723
GND_EXT_UNFILT: C57.2 CN17.2 CN17.3 L2.3 Z1.2
  other v1: 10.668,66.548 11.938,66.548 13.208,66.548 10.668,67.691 11.938,67.691 13.208,67.691 10.668,68.707 11.938,68.707 13.208,68.707
GNDDetect: CN16.11 R164.2 U21.K13 U47.5 | length 165.4
  Top Layer w0.127: v4(26.162,32.131) 26.162,33.92 26.474,34.232 R164.2@27.178,34.232 27.178,34.798 28.6,36.22 28.6,38.35 U21.K13@28.275,38.675 ; CN16.11@154.492,76.858 CN16.11@154.5,76.85
  Top Layer w0.254: v1(152.59,76.391) 153.05,76.85 CN16.11@154.5,76.85
  Signal Layer 2 w0.127: v4(26.162,32.131) 26.797,32.766 36.068,32.766 43.053,39.751 115.697,39.751 118.872,42.926 131.064,42.926 144.399,56.261 144.399,68.326 145.796,69.723 147.701,69.723 150.368,72.39 150.368,73.66 152.59,75.882 v1(152.59,76.391)
  Bottom Layer w0.127: v1(152.59,76.391) 153.352,76.391 154.036,77.074 U47.5@154.036,77.636
I2C2_SCL: CN24.6 CN30.5 Q1.3 R161.1 R206.1 R275.1 R279.2 U24.5 U48.3 | length 457.5
  Top Layer w0.127: CN24.6@12.446,23.876 20.447,23.876 v1(26.543,17.78) ; U24.5@40.4,28.5 42.239,28.5 v1(42.291,28.448) ; v1(116.078,36.957) R161.1@116.898,36.957 ; CN30.5@144.865,45.06 146.065,45.06 146.825,44.3 146.825,43.75 147.325,43.25 147.325,42.375 v1(146.775,41.825)
  Signal Layer 2 w0.127: v1(26.543,17.78) 27.178,17.145 33.782,17.145 36.449,19.812 36.449,25.781 39.116,28.448 v1(42.291,28.448) 42.545,28.194 67.281,28.194 v1(67.575,27.9) 67.575,27.375 71.975,22.975 75.2,22.975 75.569,22.606 105.791,22.606 113.792,30.607 113.792,33.592 115.633,35.433 116.586,35.433 116.713,35.56 116.713,36.322 v1(116.078,36.957) 116.078,37.128 118.625,39.675 v1(120.025,39.675) ; v1(119.888,66.675) 120.777,67.564 120.777,70.231 126.619,76.073 129.794,76.073 131.318,74.549 v1(131.318,72.898) 131.953,72.898 132.969,73.914 132.969,74.549 145.034,86.614 145.034,95.631 147.066,97.663 147.066,99.695 v1(146.812,99.949)
  Bottom Layer w0.127: R279.2@44.392,132.715 44.392,132.835 R275.1@43.242,133.985 42.799,133.985 40.386,131.572 40.386,101.6 39.497,100.711 39.497,79.248 62.738,56.007 62.738,55.753 68.707,49.784 68.707,43.557 67.85,42.7 67.85,29.575 68.225,29.2 68.225,28.55 v1(67.575,27.9) ; v1(116.078,36.957) 116.375,37.254 116.375,38.143 117.729,39.497 117.729,65.024 119.38,66.675 v1(119.888,66.675) ; v1(120.025,39.675) 122.175,39.675 126.875,44.375 144.7,44.375 146.05,43.025 146.05,42.55 v1(146.775,41.825) ; v1(131.318,72.898) 131.318,72.517 131.838,71.997 U48.3@131.838,70.751 ; v1(146.812,99.949) 146.558,100.203 146.558,117.221 137.16,126.619 137.16,136.652 132.969,140.843 132.969,154.178 136.525,157.734 145.034,157.734 145.858,156.91 R206.1@146.558,156.91 148.99,156.91 Q1.3@149.098,156.802
I2C2_SCL_C: CN2.13 Q1.2 R206.2 R211.1 | length 18.1
  Top Layer w0.508: v1(159.513,150.685) CN2.13@161.28,150.685
  Bottom Layer w0.127: R206.2@146.558,155.51 146.558,154.813 146.769,154.602 Q1.2@148.148,154.602 148.148,153.731 148.648,153.231 R211.1@148.648,152.908 148.648,152.527 148.839,152.337 156.21,152.337 157.862,150.685 v1(159.513,150.685)
I2C2_SDA: CN24.8 CN30.3 Q2.3 R35.1 R43.2 R162.1 R207.1 U24.4 U48.2 | length 451.1
  Top Layer w0.127: CN24.8@12.319,26.162 18.669,26.162 26.035,18.796 27.305,18.796 28.067,18.034 v1(28.067,17.78) ; U24.4@40.4,29.5 42.255,29.5 v1(42.291,29.464) ; v1(42.799,134.874) R43.2@43.884,134.874 ; R43.2@43.942,134.816 R43.2@43.884,134.874 ; R35.1@43.942,135.698 43.942,134.932 R43.2@43.884,134.874 ; v1(116.078,35.941) R162.1@116.898,35.941 ; CN30.3@144.865,43.79 145.91,43.79 v1(146.725,42.975)
  Signal Layer 2 w0.127: v1(28.067,17.78) 33.782,17.78 35.941,19.939 35.941,25.781 39.624,29.464 v1(42.291,29.464) 42.926,28.829 67.396,28.829 v1(67.45,28.775) 68.275,27.95 68.275,27.2 72.15,23.325 75.6,23.325 75.938,22.987 105.537,22.987 113.411,30.861 113.411,33.911 115.225,35.725 115.862,35.725 v1(116.078,35.941) 115.45,36.569 115.45,37.05 118.65,40.25 v1(120.875,40.25) ; v1(119.38,65.913) 120.142,65.913 121.158,66.929 121.158,70.104 126.746,75.692 129.667,75.692 130.81,74.549 130.81,72.263 v1(131.318,71.755) 133.35,73.787 133.35,74.295 145.415,86.36 145.415,95.504 147.828,97.917 v1(147.828,99.314)
  Bottom Layer w0.127: v1(42.799,134.874) 40.005,132.08 40.005,101.854 39.116,100.965 39.116,79.121 62.357,55.88 62.357,55.626 68.326,49.657 68.326,43.726 67.45,42.85 v1(67.45,28.775) ; v1(116.078,35.941) 116.85,36.713 116.85,37.983 118.11,39.243 118.11,64.643 v1(119.38,65.913) ; v1(120.875,40.25) 122.15,40.25 126.625,44.725 144.975,44.725 v1(146.725,42.975) ; U48.2@131.338,70.751 v1@131.338,71.481 ; Q2.3@144.018,156.802 143.91,156.91 R207.1@141.224,156.91 136.336,156.91 133.35,153.924 133.35,142.875 139.618,136.607 139.618,135.046 137.541,132.969 137.541,127 146.939,117.602 146.939,100.584 147.828,99.695 v1(147.828,99.314)
I2C2_SDA_C: CN2.14 Q2.2 R207.2 R212.1 | length 30.1
  Top Layer w0.508: CN2.14@163.83,150.685 v1(165.597,150.685)
  Bottom Layer w0.127: R207.2@141.224,155.51 141.224,154.94 141.562,154.602 Q2.2@143.068,154.602 143.068,153.033 143.192,152.908 R212.1@143.568,152.908 143.568,152.4 144.013,151.956 156.019,151.956 157.797,150.177 165.089,150.177 v1(165.597,150.685)
I2S6_CK: JP11.1 R135.2 | length 193.8
  Top Layer w0.127: R135.2@128.27,73.602 v1(128.27,74.295)
  Signal Layer 2 w0.127: v1(65.405,47.498) 66.421,46.482 110.49,46.482 122.301,58.293 122.301,68.072 128.27,74.041 v1(128.27,74.295)
  Bottom Layer w0.127: JP11.1@30.734,138.176 29.337,136.779 29.337,133.858 30.861,132.334 30.861,127.225 30.336,126.7 27.513,126.7 25.4,124.587 25.4,109.3 29.718,104.982 29.718,100.076 36.449,93.345 36.449,77.724 65.405,48.768 v1(65.405,47.498)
